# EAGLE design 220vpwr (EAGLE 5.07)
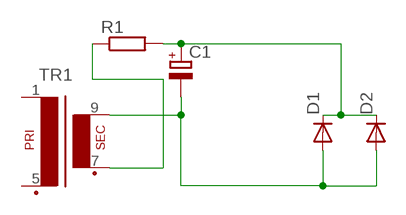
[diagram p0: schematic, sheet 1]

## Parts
C1  CPOL-EUE3.5-8  [E3,5-8]
D1  DIODE-MINIMELF  [MINIMELF]
D2  DIODE-MINIMELF  [MINIMELF]
R1  R-EU_0204/2V  [0204V]
TR1  VR11  [1WDRIVER]

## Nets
GND: C1.- D1.A D2.A TR1.9(S4)
IN: C1.+ D1.C D2.C R1.2
RED: R1.1 TR1.7(S3)
Unconnected: TR1.1 TR1.5(P2)

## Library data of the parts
C1 = rcl:CPOL-EU: POLARIZED CAPACITOR, European symbol
D1 D2 = diode-1:DIODE-: DIODE
R1 = rcl:R-EU_: RESISTOR, European symbol
TR1 = trafo:VR11: TRANSFORMER 1 primary winding, 1 secondary winding BLOCK

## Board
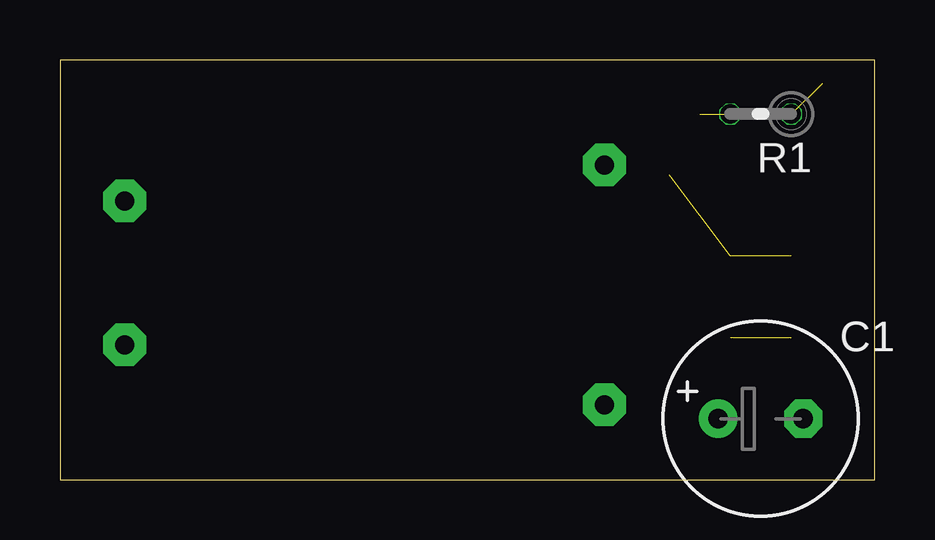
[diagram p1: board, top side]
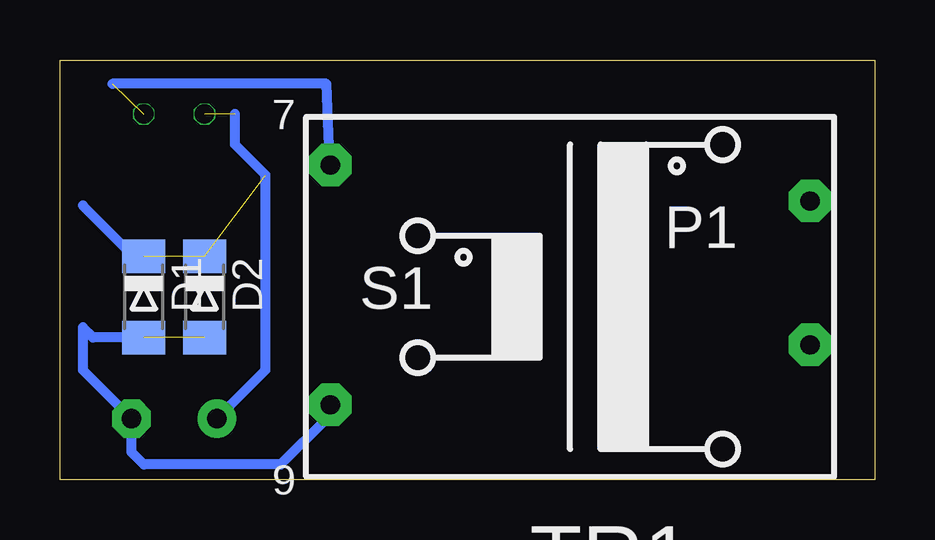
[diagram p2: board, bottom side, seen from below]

Size 33.97 x 17.5 mm. Coordinates in mm from the lower left corner, seen from the top.
Outline: 0,0 33.97,0 33.97,17.5 0,17.5 0,0
Copper layers (1*16): Top 0.035mm / dielectric 1.5mm / Bottom 0.035mm
Design rules "default": minimum track width 10mil, minimum drill 20mil, track to track 8mil, track to pad 8mil, pad to pad 8mil, via to via 8mil, smd to smd 8mil, copper to edge 40mil, drill to drill 8mil, minimum pad ring 1mil, minimum via ring 8mil, stop-mask expansion 4mil, vias tented up to drill 0mil, thermal gap 10mil

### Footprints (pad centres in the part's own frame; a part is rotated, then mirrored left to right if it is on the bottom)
E3,5-8 = drill 0.813 pad 1.6 round: + -1.778,0 | drill 0.813 pad 1.6 octagon: - 1.778,0
MINIMELF = smd 1.4 x 1.8: A 1.7,0; C -1.7,0
0204V = drill 0.813 octagon: 1 -1.27,0; 2 1.27,0
1WDRIVER = drill 0.8 pad 1.778 octagon: 1 -10,2; 5 -10,-4; 7 10,-5.5; 9 10,4.5

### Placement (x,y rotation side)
C1  29.21,2.54 0 top
D1  30.48,7.62 270 bottom
D2  27.94,7.62 270 bottom
R1  29.21,15.24 180 top
TR1  12.7,7.62 180 bottom

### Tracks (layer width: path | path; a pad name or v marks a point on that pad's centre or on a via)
GND  (1 unrouted)
  Bottom 0.406: TR1.9 22.86,2.96 22.86,2.54 24.77,0.64 30.48,0.64 30.99,1.14 C1.- 33.02,4.57 33.02,6.35 32.59,5.92 D1.A
IN  (3 unrouted)
  Bottom 0.406: 26.67,15.24 26.67,13.97 25.4,12.7 25.4,4.57 C1.+ | D1.C 30.91,9.32 33.02,11.43
RED  (1 unrouted)
  Bottom 0.406: TR1.7 22.7,12.86 22.86,16.51 31.79,16.51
